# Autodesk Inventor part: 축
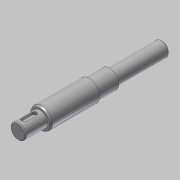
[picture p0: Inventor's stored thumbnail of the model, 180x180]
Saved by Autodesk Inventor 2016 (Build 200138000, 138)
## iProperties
Created: 2019-01
Part Number: 축
Material: 강철, 탄소
Document SubType Name: Modeling
Designer: mduedu
Density: 7.87 g/cm^3
Mass: 452.778 g
Surface Area: 120.904 cm^2
Volume: 57.5322 cm^3
Appearance: 강철
Author: mduedu
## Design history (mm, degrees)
sketch "스케치1"
  geometry: L1 (0, 0)-(26, 0); L2 (26, 0)-(26, 9); L3 (26, 9)-(0, 9); L4 (0, 9)-(0, 0); L5 (26, 0)-(84, 0); L6 (84, 0)-(84, 12.5); L7 (84, 12.5)-(26, 12.5); L8 (26, 12.5)-(26, 0); L9 (84, 0)-(108, 0); L10 (108, 0)-(108, 11); L11 (108, 11)-(84, 11); L12 (84, 11)-(84, 0); L13 (108, 0)-(170, 0); L14 (170, 0)-(170, 8.5); L15 (170, 8.5)-(108, 8.5); L16 (108, 8.5)-(108, 0)
  constraints: 32 end point, 8 parallel, 4 horizontal, 4 perpendicular
  dimensions: "d0" = 170 distance between parallel lines of L14 L4; "d2" = 26 distance of L2.end L3.end; "d3" = 24 distance of L10.end L11.end; "d4" = 62 distance of L14.end L15.end; "d5" = 18 diameter of L3 L1; "d6" = 25 diameter of L7 L5; "d7" = 22 diameter of L11 L9; "d8" = 17 diameter of L15 L13
revolve "회전1" sketch "스케치1" stored, may be unused: angle "d9" = 90 deg
node "작업 평면1"
sketch "스케치2" dims "d13" = 18
  geometry: L1 (6, -3)-(-6, -3); L2 (-6, -3)-(-6, 3); L3 (-6, 3)-(6, 3); L4 (6, 3)-(6, -3); L5 (13, 9)-(13, -9) reference; 3 further points
  constraints: 8 end point, 2 midpoint, 2 parallel, 2 vertical alignment, 1 horizontal, 1 horizontal alignment, 1 perpendicular, 4 other
  dimensions: "d10" = 6 distance between parallel lines of L3 L1; "d12" = 4 dimension on L5
extrude "돌출1" cut sketch "스케치2" distance "d14" = 3.5; taper "d15" = 0 deg
node "작업 평면2"
sketch "스케치3" dims "d19" = 20
  geometry: L1 (-21.5, -2.5)-(-6.5, -2.5); L2 (-6.5, -2.5)-(-6.5, 2.5); L3 (-6.5, 2.5)-(-21.5, 2.5); L4 (-21.5, 2.5)-(-21.5, -2.5); L5 (-31, 8.5)-(-31, -8.5) reference; 3 further points
  constraints: 8 end point, 2 midpoint, 2 parallel, 2 vertical alignment, 1 horizontal, 1 horizontal alignment, 1 perpendicular, 4 other
  dimensions: "d16" = 5 distance between parallel lines of L3 L1; "d18" = 7 dimension on L5
extrude "돌출2" cut sketch "스케치3" distance "d20" = 3; taper "d21" = 0 deg
chamfer "모따기1" distance "d22" = 1; stored, may be unused: second distance "d23" = 2, angle "d24" = 45 deg
chamfer "모따기2" distance "d25" = 2; stored, may be unused: second distance "d26" = 2, angle "d27" = 30 deg
fillet "모깎기2" dims "d30" = 2
node "솔리드1"
